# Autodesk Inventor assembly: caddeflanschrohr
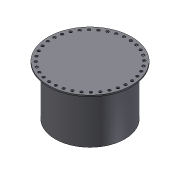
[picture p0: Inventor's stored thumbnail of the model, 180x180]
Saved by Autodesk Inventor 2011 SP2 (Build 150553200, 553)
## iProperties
Created: 2012-02
Part Number: caddeflanschrohr
Document SubType Name: Assembly
Designer: SCHALLA
Mass: 508816 g
Surface Area: 67707.6 cm^2
Volume: 64817.3 cm^3
Density: 7.85 g/cm^3
Author: SCHALLA
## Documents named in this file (4)
- W:\DCAG_CAD\3D\WORKDIR\cadde\caddeflanschrohr.iam
- W:\DCAG_CAD\3D\WORKDIR\cadde\behaelter_multi_body.ipt
- W:\DCAG_CAD\3D\WORKDIR\cadde\ROHR.ipt
- W:\DCAG_CAD\3D\WORKDIR\cadde\FLANSCH.ipt
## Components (3 placed, 3 different names)
1. behaelter_multi_body:1
2. ROHR:1
3. FLANSCH:1
